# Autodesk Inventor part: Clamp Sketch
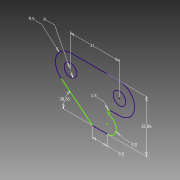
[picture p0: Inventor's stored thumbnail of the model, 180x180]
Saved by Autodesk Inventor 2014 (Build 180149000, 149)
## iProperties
Shininess: 64.0
Angle Display Precision: 2
Document Length Units: 11269
Document Angle Units: 11279
Document Time Units: 11290
Document Mass Units: 11286
Document Length Units Precision: 3
Document Angle Units Precision: 2
Created: 2002-07
Part Number: Clamp Sketch
Document SubType Name: Modeling
Designer: PN
Density: 1 g/cm^3
Description: Hinge
Mass: 25.6282 g
Surface Area: 85.6046 cm^2
Volume: 25.6282 cm^3
Material: Generic
Appearance: Rubber (Blue)
Density: 0.0
Volumn: 0.0
Area: 0.0
PropertySet Name: Model Information
Control State: 0
Master: False
Checked Out: False
LENGTH: 1.000 in
Author: PN
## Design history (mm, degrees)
sketch "Sketch1"
  geometry: L1 (0, 9.5)-(-31, 9.5); L2 (-16.999, -23.35)-(-36.607, -7.669); L3 (-7.499, -23.35)-(-16.999, -23.35); L4 (0, -9.5)-(-6.057, -9.5); C1 r 4 at (-31, 0); C2 r 4 at (0, 0); A1 r 9.5 centre (-31, 0) between (-31, 9.5) and (-36.607, -7.669); A2 r 5.5 centre (-7.499, -17.85) between (-7.499, -23.35) and (-6.366, -12.468); A3 r 1.5 centre (-6.057, -11) between (-6.057, -9.5) and (-6.366, -12.468); A4 r 9.5 centre (0, 0) between (0, -9.5) and (0, 9.5); 1 further point
  constraints: 8 end point, 8 point on circle, 7 tangent, 6 centre point, 3 coincident with centre, 2 parallel, 1 equal radius, 1 horizontal
  dimensions: "d0" = 9.5 radius of A1; "d1" = 8 diameter of C1; "d2" = 31 distance of A4.centre A1.centre; "d3" = 1.5 radius of A3; "d4" = 5.5 radius of A2; "d6" = 9.5 distance of L3.start L2.start; "d7" = 38.65 deg angle of L3 L2; "d9" = 32.85 distance between parallel lines of L3 L1
other parameters: "LENGTH" = 25.4 [user parameter]
